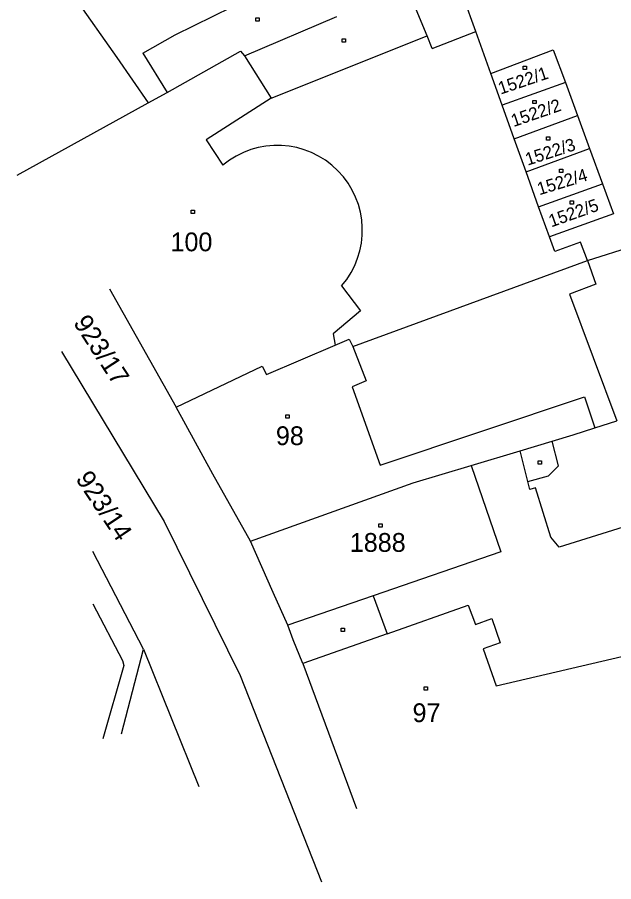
# Model space of a CAD drawing. Extents: x -711879 to -711361, y -1048782 to -1048177.
# Drawn here: x -711813.4 to -711759.4, y -1048736.3 to -1048658.1 of the extents above; entities that cross this region are included whole.
import ezdxf

# ---------------------------------------------------------------- set-up
doc = ezdxf.new("R2010")
doc.units = 0
for name, color, linetype in [('Vrstva 1', 7, 'Continuous'), ('Vrstva 14', 7, 'Continuous'), ('Vrstva 15', 7, 'Continuous'), ('Vrstva 2', 7, 'Continuous'), ('Vrstva 25', 7, 'Continuous'), ('Vrstva 46', 7, 'Continuous')]:
    doc.layers.add(name, color=color, linetype=linetype)

msp = doc.modelspace()

# ---------------------------------------------------------------- linework, layer by layer
at = {"layer": 'Vrstva 1'}
for p, q in [((-711771.92, -1048659.43), (-711774.04, -1048653.53)), ((-711792.84, -1048661.61), (-711784.49, -1048658.06)), ((-711770.55, -1048663.22), (-711771.92, -1048659.43)), ((-711799.86, -1048664.92), (-711793.2, -1048661.19)), ((-711793.2, -1048661.19), (-711792.84, -1048661.61)), ((-711770.55, -1048663.22), (-711764.9, -1048661.06)), ((-711764.9, -1048661.06), (-711763.8, -1048664.04)), ((-711769.53, -1048666.07), (-711770.55, -1048663.22)), ((-711763.8, -1048664.04), (-711769.53, -1048666.07)), ((-711763.8, -1048664.04), (-711762.71, -1048667.01)), ((-711801.56, -1048665.86), (-711799.86, -1048664.92)), ((-711813.42, -1048672.4), (-711801.56, -1048665.86)), ((-711768.43, -1048669.13), (-711769.53, -1048666.07)), ((-711768.43, -1048669.13), (-711762.71, -1048667.01)), ((-711762.71, -1048667.01), (-711761.61, -1048670)), ((-711767.36, -1048672.12), (-711768.43, -1048669.13)), ((-711767.36, -1048672.12), (-711761.61, -1048670)), ((-711761.61, -1048670), (-711760.44, -1048673.2)), ((-711766.23, -1048675.27), (-711767.36, -1048672.12)), ((-711766.23, -1048675.27), (-711760.44, -1048673.2)), ((-711760.44, -1048673.2), (-711759.45, -1048675.9)), ((-711761.8, -1048680.11), (-711740.88, -1048673.56)), ((-711765.25, -1048677.99), (-711766.23, -1048675.27)), ((-711759.45, -1048675.9), (-711765.25, -1048677.99)), ((-711764.77, -1048679.31), (-711765.25, -1048677.99)), ((-711762.45, -1048678.46), (-711764.77, -1048679.31)), ((-711761.8, -1048680.11), (-711762.45, -1048678.46)), ((-711783.06, -1048687.89), (-711761.8, -1048680.11)), ((-711761.8, -1048680.11), (-711761.04, -1048682.27)), ((-711761.04, -1048682.27), (-711763.42, -1048683.16)), ((-711805.06, -1048682.69), (-711799.03, -1048693.39)), ((-711763.42, -1048683.16), (-711759.16, -1048694.62)), ((-711784.65, -1048687.78), (-711783.39, -1048687.23)), ((-711783.39, -1048687.23), (-711783.06, -1048687.89)), ((-711790.87, -1048690.42), (-711784.65, -1048687.78)), ((-711809.43, -1048688.36), (-711800.12, -1048703.73)), ((-711799.03, -1048693.39), (-711791.24, -1048689.67)), ((-711791.24, -1048689.67), (-711790.87, -1048690.42)), ((-711795.72, -1048699.44), (-711799.03, -1048693.39)), ((-711761.13, -1048695.26), (-711759.16, -1048694.62)), ((-711763.1, -1048695.9), (-711761.13, -1048695.26)), ((-711767.9, -1048697.33), (-711764.99, -1048696.46)), ((-711764.99, -1048696.46), (-711763.1, -1048695.9)), ((-711764.44, -1048698.68), (-711764.99, -1048696.46)), ((-711772.34, -1048698.66), (-711767.9, -1048697.33)), ((-711777.58, -1048700.23), (-711772.34, -1048698.66)), ((-711772.34, -1048698.66), (-711769.65, -1048706.47)), ((-711765.32, -1048699.59), (-711764.44, -1048698.68)), ((-711739.72, -1048698.33), (-711764.36, -1048706.06)), ((-711792.32, -1048705.51), (-711795.72, -1048699.44)), ((-711767.21, -1048700.12), (-711765.32, -1048699.59)), ((-711792.32, -1048705.51), (-711777.58, -1048700.23)), ((-711767.03, -1048700.83), (-711767.21, -1048700.12)), ((-711766.52, -1048700.67), (-711767.03, -1048700.83)), ((-711765.12, -1048705.13), (-711766.52, -1048700.67)), ((-711800.12, -1048703.73), (-711793.25, -1048717.65)), ((-711764.36, -1048706.06), (-711765.12, -1048705.13)), ((-711790.25, -1048710.14), (-711792.32, -1048705.51)), ((-711801.98, -1048715.27), (-711806.59, -1048706.45)), ((-711769.65, -1048706.47), (-711781.21, -1048710.45)), ((-711788.93, -1048713.11), (-711790.25, -1048710.14)), ((-711781.21, -1048710.45), (-711779.93, -1048713.87)), ((-711806.58, -1048711.16), (-711803.88, -1048716.31)), ((-711788.44, -1048714.43), (-711788.93, -1048713.11)), ((-711787.56, -1048716.57), (-711788.44, -1048714.43)), ((-711779.93, -1048713.87), (-711787.56, -1048716.57)), ((-711803.98, -1048722.92), (-711801.98, -1048715.27)), ((-711801.98, -1048715.27), (-711797, -1048727.68)), ((-711803.77, -1048716.76), (-711805.69, -1048723.37)), ((-711803.88, -1048716.31), (-711803.77, -1048716.76)), ((-711787.56, -1048716.57), (-711782.71, -1048729.69)), ((-711793.25, -1048717.65), (-711785.87, -1048736.3))]:
    msp.add_line(p, q, dxfattribs=at)
at = {"layer": 'Vrstva 2'}
for p, q in [((-711799.14, -1048659.71), (-711786.69, -1048653.59)), ((-711809.27, -1048654.86), (-711804.42, -1048661.76)), ((-711776.33, -1048659.82), (-711778.21, -1048655.25)), ((-711802.06, -1048661.36), (-711799.14, -1048659.71)), ((-711790.45, -1048665.43), (-711776.33, -1048659.82)), ((-711775.86, -1048660.96), (-711776.33, -1048659.82)), ((-711775.86, -1048660.96), (-711771.92, -1048659.43)), ((-711802.06, -1048661.36), (-711799.86, -1048664.92)), ((-711804.42, -1048661.76), (-711801.56, -1048665.86)), ((-711792.84, -1048661.61), (-711790.45, -1048665.43)), ((-711790.45, -1048665.43), (-711796.31, -1048669.21)), ((-711796.31, -1048669.21), (-711794.81, -1048671.51)), ((-711784.06, -1048682.42), (-711782.34, -1048684.67)), ((-711782.34, -1048684.67), (-711784.83, -1048686.76)), ((-711784.83, -1048686.76), (-711784.65, -1048687.78)), ((-711783.06, -1048687.89), (-711781.85, -1048691)), ((-711781.85, -1048691), (-711783.1, -1048691.54)), ((-711783.1, -1048691.54), (-711780.57, -1048698.63)), ((-711780.57, -1048698.63), (-711762.09, -1048692.45)), ((-711762.09, -1048692.45), (-711761.13, -1048695.26)), ((-711767.21, -1048700.12), (-711767.9, -1048697.33)), ((-711781.21, -1048710.45), (-711788.93, -1048713.11)), ((-711779.93, -1048713.87), (-711772.62, -1048711.29)), ((-711772.62, -1048711.29), (-711771.94, -1048713.04)), ((-711771.94, -1048713.04), (-711770.46, -1048712.51)), ((-711770.46, -1048712.51), (-711769.7, -1048714.7)), ((-711769.7, -1048714.7), (-711771.24, -1048715.24)), ((-711771.24, -1048715.24), (-711770.07, -1048718.6)), ((-711770.07, -1048718.6), (-711757.78, -1048715.73))]:
    msp.add_line(p, q, dxfattribs=at)
msp.add_arc((-711789.869, -1048677.392), 7.682, 319.12208, 130.03145, dxfattribs=at)
at = {"layer": 'Vrstva 25'}
for p, q in [((-711791.83, -1048658.17), (-711791.53, -1048658.17)), ((-711791.83, -1048658.47), (-711791.83, -1048658.17)), ((-711791.53, -1048658.17), (-711791.53, -1048658.47)), ((-711791.53, -1048658.47), (-711791.83, -1048658.47)), ((-711784.02, -1048660.07), (-711783.72, -1048660.07)), ((-711784.02, -1048660.37), (-711784.02, -1048660.07)), ((-711783.72, -1048660.37), (-711784.02, -1048660.37)), ((-711783.72, -1048660.07), (-711783.72, -1048660.37)), ((-711767.63, -1048662.55), (-711767.33, -1048662.55)), ((-711767.63, -1048662.85), (-711767.63, -1048662.55)), ((-711767.33, -1048662.85), (-711767.63, -1048662.85)), ((-711767.33, -1048662.55), (-711767.33, -1048662.85)), ((-711766.74, -1048665.64), (-711766.44, -1048665.64)), ((-711766.74, -1048665.94), (-711766.74, -1048665.64)), ((-711766.44, -1048665.94), (-711766.74, -1048665.94)), ((-711766.44, -1048665.64), (-711766.44, -1048665.94)), ((-711765.52, -1048668.93), (-711765.22, -1048668.93)), ((-711765.52, -1048669.23), (-711765.52, -1048668.93)), ((-711765.22, -1048669.23), (-711765.52, -1048669.23)), ((-711765.22, -1048668.93), (-711765.22, -1048669.23)), ((-711764.34, -1048671.87), (-711764.04, -1048671.87)), ((-711764.34, -1048672.17), (-711764.34, -1048671.87)), ((-711764.04, -1048672.17), (-711764.34, -1048672.17)), ((-711764.04, -1048671.87), (-711764.04, -1048672.17)), ((-711763.36, -1048674.73), (-711763.06, -1048674.73)), ((-711763.36, -1048675.03), (-711763.36, -1048674.73)), ((-711763.06, -1048674.73), (-711763.06, -1048675.03)), ((-711763.06, -1048675.03), (-711763.36, -1048675.03)), ((-711797.68, -1048675.57), (-711797.38, -1048675.57)), ((-711797.68, -1048675.87), (-711797.68, -1048675.57)), ((-711797.38, -1048675.87), (-711797.68, -1048675.87)), ((-711797.38, -1048675.57), (-711797.38, -1048675.87)), ((-711789.12, -1048694.08), (-711788.82, -1048694.08)), ((-711789.12, -1048694.38), (-711789.12, -1048694.08)), ((-711788.82, -1048694.08), (-711788.82, -1048694.38)), ((-711788.82, -1048694.38), (-711789.12, -1048694.38)), ((-711766.26, -1048698.23), (-711765.96, -1048698.23)), ((-711766.26, -1048698.53), (-711766.26, -1048698.23)), ((-711765.96, -1048698.23), (-711765.96, -1048698.53)), ((-711765.96, -1048698.53), (-711766.26, -1048698.53)), ((-711780.69, -1048703.93), (-711780.39, -1048703.93)), ((-711780.69, -1048704.23), (-711780.69, -1048703.93)), ((-711780.39, -1048704.23), (-711780.69, -1048704.23)), ((-711780.39, -1048703.93), (-711780.39, -1048704.23)), ((-711784.1, -1048713.38), (-711783.8, -1048713.38)), ((-711784.1, -1048713.68), (-711784.1, -1048713.38)), ((-711783.8, -1048713.68), (-711784.1, -1048713.68)), ((-711783.8, -1048713.38), (-711783.8, -1048713.68)), ((-711776.58, -1048718.67), (-711776.28, -1048718.67)), ((-711776.58, -1048718.97), (-711776.58, -1048718.67)), ((-711776.28, -1048718.97), (-711776.58, -1048718.97)), ((-711776.28, -1048718.67), (-711776.28, -1048718.97))]:
    msp.add_line(p, q, dxfattribs=at)
at = {"layer": 'Vrstva 46'}
for p, q in [((-711799.14, -1048659.71), (-711799.14, -1048659.71)), ((-711802.06, -1048661.36), (-711802.06, -1048661.36)), ((-711793.2, -1048661.19), (-711793.2, -1048661.19)), ((-711804.42, -1048661.76), (-711804.42, -1048661.76)), ((-711799.86, -1048664.92), (-711799.86, -1048664.92)), ((-711781.85, -1048691), (-711781.85, -1048691)), ((-711767.9, -1048697.33), (-711767.9, -1048697.33)), ((-711772.34, -1048698.66), (-711772.34, -1048698.66)), ((-711795.72, -1048699.44), (-711795.72, -1048699.44)), ((-711777.58, -1048700.23), (-711777.58, -1048700.23)), ((-711765.18, -1048704.93), (-711765.18, -1048704.93)), ((-711772.62, -1048711.29), (-711772.62, -1048711.29)), ((-711779.93, -1048713.87), (-711779.93, -1048713.87)), ((-711787.56, -1048716.57), (-711787.56, -1048716.57))]:
    msp.add_line(p, q, dxfattribs=at)

# ---------------------------------------------------------------- texts
at = {"layer": 'Vrstva 14'}
for s, rotation, p in [('923/17', 303.06906, (-711808.4, -1048685.75)), ('923/14', 303.75009, (-711808.19, -1048699.87))]:
    msp.add_text(s, height=1.7, rotation=rotation, dxfattribs=at).set_placement(p)
at = {"layer": 'Vrstva 15'}
for s, rotation, p in [('1522/1', 18.56034, (-711769.668, -1048665.125)), ('1522/2', 19.06146, (-711768.494, -1048668.065)), ('1522/3', 18.04734, (-711767.222, -1048671.555)), ('1522/4', 16.94079, (-711766.162, -1048674.23)), ('1522/5', 19.54638, (-711765.08, -1048677.135))]:
    msp.add_text(s, height=1.14, rotation=rotation, dxfattribs=at).set_placement(p)
for s, p in [('100', (-711799.55, -1048679.29)), ('98', (-711790.01, -1048696.82)), ('1888', (-711783.32, -1048706.47)), ('97', (-711777.64, -1048721.87))]:
    msp.add_text(s, height=1.7, dxfattribs=at).set_placement(p)

doc.saveas('drawing.dxf')
